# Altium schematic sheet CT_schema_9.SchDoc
size 147 x 119 mm
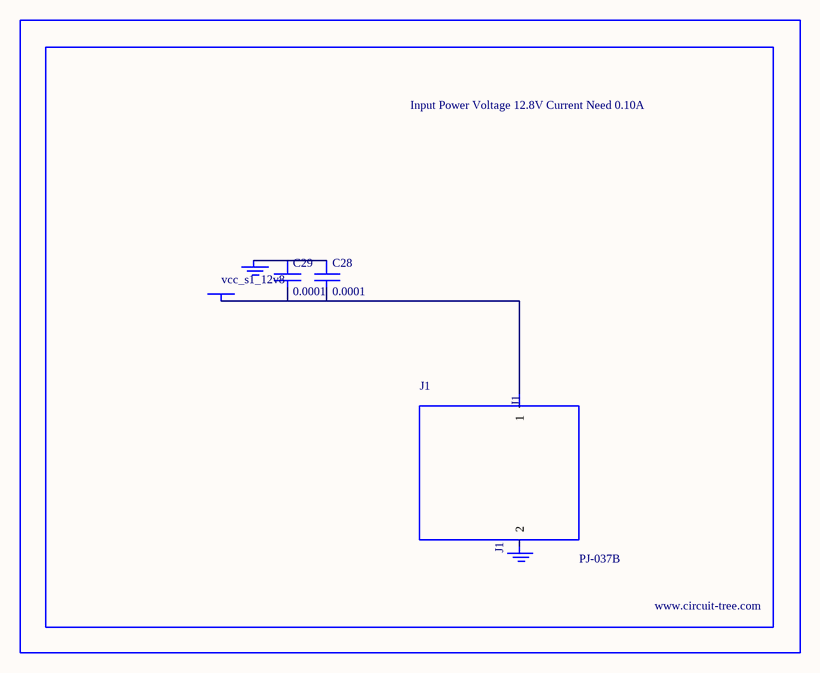
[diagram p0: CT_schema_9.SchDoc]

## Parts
BORDER8  (no value)
C28  0.0001  [EXV-9H]
C29  0.0001  [EXV-9H]
GND_INSTANCE_8_0  (no value)
GND_INSTANCE_8_1  (no value)
J1  PJ-037B  [PJ-037B_PACKAGE]
POWER_INSTANCE_8_0  vcc_s1_12v8

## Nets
NetC28_1: C28.1 C29.1 GND_INSTANCE_8_0.0(GND)
NetC28_2: C28.2 C29.2 J1.1 POWER_INSTANCE_8_0.0(PWR)

Not connected (* = marked no-connect by the designer): GND_INSTANCE_8_1 0(GND); J1 2

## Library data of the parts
BORDER8 = BORDER_PAGE8
C28 C29 = EDK107M035A9HAA
GND_INSTANCE_8_0 GND_INSTANCE_8_1 = GND
POWER_INSTANCE_8_0 = PWR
